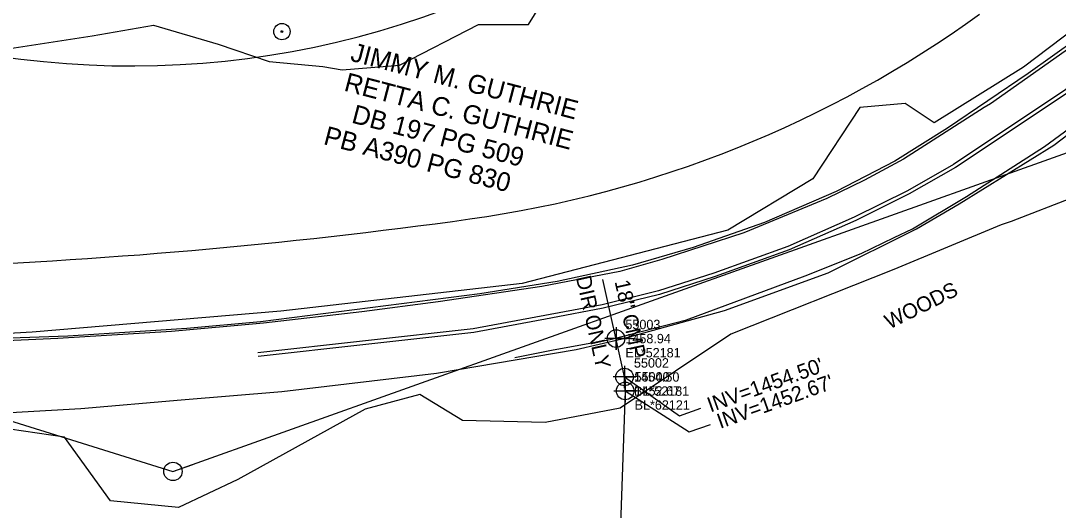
# Model space of a CAD drawing. Extents: x 1004911 to 1009660, y 551419 to 554278.
# Drawn here: x 1008435.2 to 1008711.1, y 551629 to 551759.3 of the extents above; entities that cross this region are included whole.
import ezdxf

# ---------------------------------------------------------------- set-up
doc = ezdxf.new("R2010")
doc.units = 0
for name, color, linetype in [('Default', 7, 'Continuous'), ('Exist Hydro Jurisdictional Stream or Body of Water', 7, 'Continuous'), ('Exist Property Deed Book Text', 7, 'Continuous'), ('Exist Property Owner Text', 7, 'Continuous'), ('Exist Right of Way Line', 7, 'Continuous'), ('Exist Roads EOT', 7, 'Continuous'), ('Exist Structure Minor Pipes CMP 18 Inch', 7, 'Continuous'), ('Exist Structure Minor Pipes CMP 18 Inch Cogo Comment', 7, 'Continuous'), ('Exist Structure Minor Pipes CMP 18 Inch Cogo Elevation', 7, 'Continuous'), ('Exist Structure Minor Pipes CMP 18 Inch Cogo Number', 7, 'Continuous'), ('Exist Structure Minor Pipes CMP 18 Inch Cogo Point CELL', 7, 'Continuous'), ('Exist Structure Minor Pipes CMP 18 Inch Invert', 7, 'Continuous'), ('Exist Structure Minor Pipes CMP 18 Inch Leader', 7, 'Continuous'), ('Exist Structure Minor Pipes CMP 18 Inch Text', 7, 'Continuous'), ('Exist Structure Minor Pipes HDPE 12 Inch', 7, 'Continuous'), ('Exist Structure Minor Pipes HDPE 12 Inch Cogo Comment', 7, 'Continuous'), ('Exist Structure Minor Pipes HDPE 12 Inch Cogo Elevation', 7, 'Continuous'), ('Exist Structure Minor Pipes HDPE 12 Inch Cogo Number', 7, 'Continuous'), ('Exist Structure Minor Pipes HDPE 12 Inch Cogo Point CELL', 7, 'Continuous'), ('Exist Structure Minor Pipes HDPE 12 Inch Invert', 7, 'Continuous'), ('Exist Structure Minor Pipes HDPE 12 Inch Leader', 7, 'Continuous'), ('Exist Vegetation Woods Line Text', 7, 'Continuous'), ('Sheet Plan Layout CELL', 7, 'Continuous'), ('Sheet Plot Border Inside CELL', 7, 'Continuous')]:
    doc.layers.add(name, color=color, linetype=linetype)

msp = doc.modelspace()

# ---------------------------------------------------------------- linework, layer by layer
at = {"layer": 'Default'}
msp.add_lwpolyline([(1007889.69, 551637.93), (1008120.9, 551750.24), (1008475.69, 551639.38), (1008762.04, 551741.57), (1009077.06, 551997.55)], dxfattribs=at)
at = {"layer": 'Exist Hydro Jurisdictional Stream or Body of Water'}
for q in [(1008481, 551641.24), (1008475.69, 551639.38)]:
    msp.add_line((1008475.69, 551639.38), q, dxfattribs=at)
msp.add_circle((1008475.69, 551639.38), 2.45, dxfattribs=at)
at = {"layer": 'Exist Right of Way Line'}
msp.add_line((1008366.29, 551757.66), (1008435.21, 551749.1), dxfattribs=at)
for centre, radius, start, end in [((1008464.59, 551985.79), 238.5, 262.9254, 309.2775), ((1008513.05, 552005.79), 302.1, 277.9086, 305.9002), ((1008353.66, 553153.14), 1460.47, 272.07609, 277.90864)]:
    msp.add_arc(centre, radius, start, end, dxfattribs=at)
at = {"layer": 'Exist Roads EOT'}
for points in [[(1008907.36, 551903.22), (1008879.41, 551880.66), (1008855.98, 551861.62), (1008839.78, 551848.78), (1008823.61, 551836.36), (1008802.49, 551819.8), (1008768.8, 551792.98), (1008745.04, 551774.96), (1008718.97, 551755.48), (1008693.09, 551737.17), (1008691.4, 551736.19), (1008669.93, 551722.52), (1008659.64, 551716.93), (1008649.58, 551711.97), (1008627.47, 551702.88), (1008605.69, 551695.79), (1008594.51, 551692.62), (1008573.77, 551688.58), (1008546.23, 551684.51), (1008525.88, 551681.81), (1008499.74, 551678.82), (1008475.29, 551676.6), (1008445.08, 551674.72), (1008415.8, 551673.45)], [(1008912.31, 551896.8), (1008898.31, 551885.23), (1008876.2, 551867.75), (1008862.13, 551856.44), (1008833.3, 551833.81), (1008812.05, 551817), (1008790.81, 551800.18), (1008763.05, 551778.61), (1008738.1, 551759.79), (1008713.16, 551740.98), (1008683.27, 551721.08), (1008671.01, 551714.09), (1008656.85, 551707.01), (1008639.19, 551699.28), (1008619.53, 551692.16), (1008604.79, 551687.4), (1008589.87, 551683.74), (1008575.99, 551681.1), (1008555.57, 551677.32), (1008526.9, 551674.13), (1008498.23, 551670.93)], [(1008912.93, 551896.05), (1008898.92, 551884.47), (1008876.81, 551866.99), (1008862.74, 551855.68), (1008833.9, 551833.05), (1008812.65, 551816.23), (1008791.4, 551799.42), (1008763.64, 551777.84), (1008738.68, 551759.01), (1008713.72, 551740.19), (1008683.78, 551720.26), (1008671.47, 551713.24), (1008657.26, 551706.13), (1008639.55, 551698.38), (1008619.85, 551691.25), (1008605.06, 551686.46), (1008590.07, 551682.79), (1008576.17, 551680.15), (1008555.71, 551676.36), (1008527.02, 551673.16), (1008498.34, 551669.96)], [(1008566.64, 551669.73), (1008576.82, 551671.7), (1008592, 551674.49), (1008612.26, 551679.71), (1008643.79, 551691.47), (1008658.72, 551697.34), (1008667.45, 551701.6), (1008672.35, 551703.92), (1008686.7, 551712.54), (1008707.47, 551725.85), (1008737.45, 551747.81), (1008756.6, 551761.54), (1008783.28, 551782.1), (1008802.4, 551797.04), (1008821.67, 551812.04), (1008848.51, 551833.39), (1008865.56, 551846.23), (1008887.7, 551864.73), (1008906.57, 551880.14), (1008917.93, 551889.42)]]:
    msp.add_lwpolyline(points, dxfattribs=at)
for radius in [2.18, 0.24]:
    msp.add_circle((1008504.67, 551756.42), radius, dxfattribs=at)
at = {"layer": 'Exist Structure Minor Pipes CMP 18 Inch'}
msp.add_line((1008595.79, 551664.51), (1008590.03, 551690.48), dxfattribs=at)
at = {"layer": 'Exist Structure Minor Pipes CMP 18 Inch Cogo Point CELL'}
for points in [[(1008593.52, 551677.73), (1008593.52, 551671.73), (1008593.52, 551674.73), (1008596.52, 551674.73), (1008590.52, 551674.73)], [(1008595.79, 551667.51), (1008595.79, 551661.51), (1008595.79, 551664.51), (1008598.79, 551664.51), (1008592.79, 551664.51)]]:
    msp.add_lwpolyline(points, dxfattribs=at)
for centre in [(1008593.52, 551674.73), (1008595.79, 551664.51)]:
    msp.add_circle(centre, 2.34, dxfattribs=at)
at = {"layer": 'Exist Structure Minor Pipes CMP 18 Inch Leader'}
msp.add_lwpolyline([(1008595.79, 551664.51), (1008610.44, 551654.21), (1008616.08, 551656.24)], dxfattribs=at)
at = {"layer": 'Exist Structure Minor Pipes HDPE 12 Inch'}
msp.add_line((1008595.96, 551660.81), (1008592.94, 551575.98), dxfattribs=at)
at = {"layer": 'Exist Structure Minor Pipes HDPE 12 Inch Cogo Point CELL'}
msp.add_lwpolyline([(1008592.96, 551660.81), (1008598.96, 551660.81), (1008595.96, 551660.81), (1008595.96, 551663.81), (1008595.96, 551657.81)], dxfattribs=at)
msp.add_circle((1008595.96, 551660.81), 2.34, dxfattribs=at)
at = {"layer": 'Exist Structure Minor Pipes HDPE 12 Inch Leader'}
msp.add_lwpolyline([(1008595.96, 551660.81), (1008613.01, 551649.9), (1008618.66, 551651.91)], dxfattribs=at)
at = {"layer": 'Sheet Plan Layout CELL'}
for points in [[(1008907.11, 551903.38), (1008877.31, 551879.59), (1008851.37, 551858.85), (1008822.68, 551836.33), (1008793.06, 551813.04), (1008765.92, 551791.92), (1008729.03, 551763.74), (1008703.1, 551745.29), (1008681.67, 551730.77), (1008667.7, 551721.91), (1008652.09, 551713.87), (1008633.01, 551705.65), (1008614.06, 551698.98), (1008597.93, 551694.24), (1008577.87, 551689.89), (1008557.3, 551686.65), (1008528.14, 551682.94), (1008498.99, 551679.22), (1008479.34, 551677.44), (1008447.75, 551675.38), (1008414.74, 551674.2)], [(1008424.58, 551654.63), (1008451.18, 551656.16), (1008477.9, 551658.42), (1008504.62, 551660.69), (1008545.78, 551665.53), (1008582.94, 551671.86), (1008595.16, 551674.7), (1008622.33, 551682.2), (1008649.94, 551692.27), (1008673.43, 551703.94), (1008684.82, 551710.61), (1008709.93, 551726.23), (1008734.87, 551745.19), (1008759.87, 551763.36), (1008797.37, 551791.77), (1008829.87, 551816.56), (1008849.37, 551833.07), (1008864.53, 551844.74), (1008903.81, 551876.93), (1008918.25, 551888.99)]]:
    msp.add_lwpolyline(points, dxfattribs=at)
at = {"layer": 'Sheet Plot Border Inside CELL'}
for points in [[(1008898.2, 551898.73), (1008880.71, 551886.66), (1008868.31, 551886.49), (1008856.08, 551882.92), (1008843.34, 551869.5), (1008830.77, 551855.73), (1008819.23, 551849.61), (1008817.87, 551846.21), (1008815.49, 551833.98), (1008784.24, 551810.86), (1008769.46, 551814.43), (1008763.18, 551806.62), (1008757.23, 551788.94), (1008701.87, 551746.96), (1008678.09, 551732.18), (1008670.45, 551737.27), (1008658.39, 551736.25), (1008645.82, 551717.22), (1008623.23, 551703.62), (1008568.54, 551689.35), (1008504.34, 551682.04), (1008438.28, 551676.43), (1008416.2, 551675.24)], [(1008432.33, 551751.89), (1008454.24, 551755.29), (1008470.55, 551758.18), (1008487.7, 551753.08), (1008501.29, 551748.49), (1008515.55, 551747.13), (1008520.65, 551746.28), (1008535.93, 551747.47), (1008556.99, 551758.35), (1008570.24, 551758.35), (1008580.09, 551774.32), (1008611.51, 551795.74), (1008617.46, 551798.46), (1008622.55, 551799.65), (1008635.46, 551801.69), (1008645.48, 551807.3), (1008646.16, 551823.27), (1008658.56, 551837.89), (1008673.5, 551835), (1008692.53, 551835.51), (1008688.79, 551847.74), (1008700.85, 551855.73), (1008713.08, 551868.82)], [(1008732.49, 551719), (1008698.61, 551705.91), (1008695.94, 551705.02), (1008667.4, 551693.12), (1008624.01, 551675.87), (1008594.58, 551656.24), (1008574.67, 551652.38), (1008552.68, 551652.97), (1008541.38, 551659.81), (1008526.82, 551655.95), (1008492.94, 551637.21), (1008477.18, 551629.77), (1008459.05, 551631.56), (1008446.87, 551648.51), (1008432.3, 551650.59)]]:
    msp.add_lwpolyline(points, dxfattribs=at)

# ---------------------------------------------------------------- texts
at = {"layer": 'Exist Property Deed Book Text'}
for s, p in [('DB 197 PG 509', (1008522.95, 551732.24)), ('PB A390 PG 830', (1008515.48, 551726.52))]:
    msp.add_text(s, height=5, rotation=345.3339, dxfattribs=at).set_placement(p)
at = {"layer": 'Exist Property Owner Text'}
for s, p in [('JIMMY M. GUTHRIE', (1008522.63, 551748.71)), ('RETTA C. GUTHRIE', (1008520.94, 551740.75))]:
    msp.add_text(s, height=5, rotation=345.3339, dxfattribs=at).set_placement(p)
at = {"layer": 'Exist Structure Minor Pipes CMP 18 Inch Cogo Comment'}
for s, p in [('EL*52181', (1008596.02, 551669.73)), ('BL*52181', (1008598.29, 551659.51))]:
    msp.add_text(s, height=2.5, dxfattribs=at).set_placement(p)
at = {"layer": 'Exist Structure Minor Pipes CMP 18 Inch Cogo Elevation'}
for s, p in [('1458.94', (1008596.02, 551673.48)), ('1454.50', (1008598.29, 551663.26))]:
    msp.add_text(s, height=2.5, dxfattribs=at).set_placement(p)
at = {"layer": 'Exist Structure Minor Pipes CMP 18 Inch Cogo Number'}
for s, p in [('55003', (1008596.02, 551677.23)), ('55002', (1008598.29, 551667.01))]:
    msp.add_text(s, height=2.5, dxfattribs=at).set_placement(p)
at = {"layer": 'Exist Structure Minor Pipes CMP 18 Inch Invert'}
msp.add_text("INV=1454.50'", height=4, rotation=19.8347, dxfattribs=at).set_placement((1008618.64, 551655.04))
at = {"layer": 'Exist Structure Minor Pipes CMP 18 Inch Text'}
for s, p in [('DIR ONLY', (1008582.84, 551691.03)), ('18" CMP', (1008593.12, 551689.91))]:
    msp.add_text(s, height=4, rotation=282.5026, dxfattribs=at).set_placement(p)
at = {"layer": 'Exist Structure Minor Pipes HDPE 12 Inch Cogo Comment'}
msp.add_text('BL*62121', height=2.5, dxfattribs=at).set_placement((1008598.46, 551655.81))
at = {"layer": 'Exist Structure Minor Pipes HDPE 12 Inch Cogo Elevation'}
msp.add_text('1452.67', height=2.5, dxfattribs=at).set_placement((1008598.46, 551659.56))
at = {"layer": 'Exist Structure Minor Pipes HDPE 12 Inch Cogo Number'}
msp.add_text('55000', height=2.5, dxfattribs=at).set_placement((1008598.46, 551663.31))
at = {"layer": 'Exist Structure Minor Pipes HDPE 12 Inch Invert'}
msp.add_text("INV=1452.67'", height=4, rotation=19.58, dxfattribs=at).set_placement((1008621.22, 551650.7))
at = {"layer": 'Exist Vegetation Woods Line Text'}
msp.add_text('WOODS', height=4, rotation=26.5751, dxfattribs=at).set_placement((1008666.24, 551677.14))

doc.saveas('drawing.dxf')
